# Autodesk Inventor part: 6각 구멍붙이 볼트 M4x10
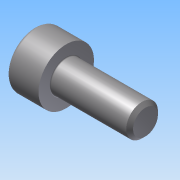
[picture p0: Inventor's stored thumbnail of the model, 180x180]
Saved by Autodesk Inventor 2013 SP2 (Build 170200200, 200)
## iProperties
Created: 2026-07
Part Number: 6각 구멍붙이 볼트 M4x10
Material: Generic
Document SubType Name: Modeling
Designer: 601
Density: 1 g/cm^3
Author: 601
변환 표준: STEP AP214IS
전처리기: Build: 200, Release: 2013 SP2 Update 6 - Date: Thu 07/17/2014
전송 단위: 밀리미터
불확실성: 0.01
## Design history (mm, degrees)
node "6각 구멍붙이 볼트 M4x101"
body "Solid1"
node "기준1"
